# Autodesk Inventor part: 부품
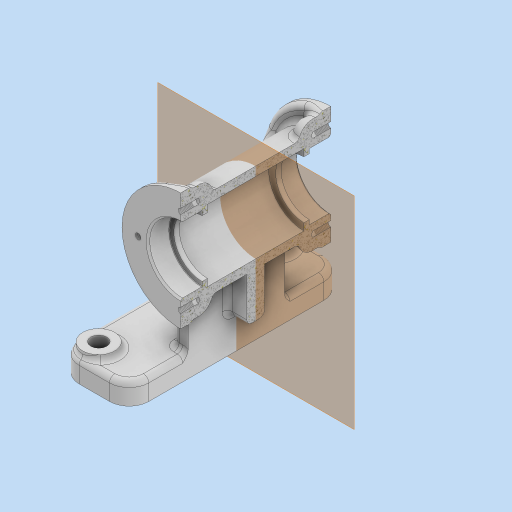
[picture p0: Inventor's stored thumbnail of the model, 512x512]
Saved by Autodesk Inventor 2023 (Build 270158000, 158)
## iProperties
Created: 2026-06
Part Number: 부품
Material: 일반
Document SubType Name: Modeling
Designer: home
Density: 1 g/cm^3
Appearance: 기본값
Author: home
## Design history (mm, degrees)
sketch "스케치1"
  geometry: L1 (50, 60)-(-50, 60); L2 (-50, 60)-(-50, -60); L3 (-50, -60)-(50, -60); L4 (50, -60)-(50, 60); L5 (50, 60)-(-50, -60); L6 (-50, 60)-(50, -60); 1 further point
  constraints: 12 end point, 2 midpoint, 2 parallel, 1 horizontal, 1 perpendicular
  dimensions: "d0" = 100 distance of L2.end L3.end; "d1" = 120 distance of L3.end L1.start
extrude "돌출1" new body sketch "스케치1" distance "d2" = 12; taper "d3" = 0 deg
sketch "스케치2"
  geometry: L1 (-11, 60)-(-11, -60); L2 (11, 60)-(11, -60); L3 (-50, 60)-(-50, -60) reference; L4 (50, -60)-(50, 60) reference; L5 (50, 60)-(-50, 60) reference; L6 (-11, 60)-(11, 60); L7 (-50, -60)-(50, -60) reference; L8 (-11, -60)-(11, -60); 1 further point
  constraints: 8 end point, 4 point on line, 2 vertical
  dimensions: "d4" = 39 distance between parallel lines of L1 L3; "d5" = 39 distance between parallel lines of L2 L4
extrude "돌출2" cut sketch "스케치2" extent not by distance; stored distance "d6" = 0; taper "d7" = 0 deg
node "작업 평면1"
node "작업 평면2"
sketch "스케치7"
  geometry: C1 r 33 at (0, 70); 1 further point
  constraints: 1 centre point, 1 vertical alignment
  dimensions: "d16" = 66 diameter of C1; "d17" = 70 distance of point (0, 0) C1.centre
extrude "돌출3" join sketch "스케치7" distance "d18" = 5; taper "d19" = 0 deg
sketch "스케치8"
  geometry: L1 (37, -37)-(103, -37) reference; L2 (37, 37)-(103, 37) reference; L3 (70, -37)-(70, 37); L4 (95, -37)-(95, 37); L5 (95, -37)-(70, -37); L6 (70, 37)-(70, -37); L7 (70, 37)-(95, 37); L8 (70, -37)-(70, 37); L9 (103, 42)-(37, 42) reference; 1 further point
  constraints: 12 end point, 3 collinear, 2 midpoint, 2 perpendicular, 2 point on line
  dimensions: "d20" = 50 diameter of L4 L3
revolve "회전2" sketch "스케치8" stored, may be unused: angle "d21" = 90 deg
sketch "스케치11"
  geometry: L1 (103, 42)-(37, 42) reference; L2 (88.5, 42)-(88.5, 30); L3 (88.5, 30)-(86, 30); L4 (86, 30)-(86, 27); L5 (86, 27)-(90, 27); L6 (90, 27)-(90, 0); L7 (95, -37)-(95, 37) reference; L8 (95, 0)-(37, 0); L9 (70, 42)-(70, -47.015); L10 (88.5, 42)-(70, 42); L11 (37, 37)-(103, 37) reference; L12 (70, 42)-(70, 0); L13 (70, 0)-(90, 0); 1 further point
  constraints: 20 end point, 5 perpendicular, 4 point on line, 2 midpoint, 1 collinear, 1 horizontal, 1 parallel, 1 vertical
  dimensions: "d22" = 32 diameter of L4 L9; "d23" = 37 diameter of L2 L9; "d24" = 12 distance of L2.start L2.end; "d25" = 27 distance of L5.end L6.end; "d26" = 40 diameter of L6 L9
revolve "회전3" sketch "스케치11" stored, may be unused: angle "d27" = 90 deg
fillet "모깎기1" dims "d28" = 11
sketch "스케치13"
  geometry: L1 (11, 27)-(19, 27); L2 (19, 27)-(19, -27); L3 (19, -27)-(11, -27); L4 (11, -27)-(11, 27); L5 (11, 49)-(11, -49) reference; 2 further points
  constraints: 8 end point, 2 midpoint, 2 parallel, 1 collinear, 1 horizontal, 1 perpendicular
  dimensions: "d32" = 54 distance of L3.end L1.start; "d41" = 8 distance between parallel lines of L2 L4
extrude "돌출4" join sketch "스케치13" stored distance "d34" = 5; taper "d35" = 0 deg
sketch "스케치14"
  geometry: L1 (24.587, 65.475)-(43, 12); L2 (19, 12)-(19, 53.752) reference; L3 (19, 12)-(19, 53.752); L4 (19, 12)-(43, 12); L5 (50, 12)-(50, 0) reference; A1 r 25 centre (0, 70) between (19, 53.752) and (19, 53.752) reference; A2 r 25 centre (0, 70) between (19, 53.752) and (24.587, 65.475); 2 further points
  constraints: 6 end point, 4 point on circle, 1 centre point, 1 coincident, 1 horizontal, 1 point on line
  dimensions: "d44" = 19 deg angle of L2 L1; "d45" = 7 distance from line of L1.end L5
extrude "돌출5" join sketch "스케치14" stored distance "d38" = 10; taper "d39" = 0 deg
fillet "모깎기3" dims "d40" = 3
sketch "스케치15"
  geometry: L1 (-39, -49)-(39, -49); L2 (39, -49)-(39, 49); L3 (39, 49)-(-39, 49); L4 (-39, 49)-(-39, -49); L5 (-39, -49)-(39, 49); L6 (39, -49)-(-39, 49); C1 r 9 at (-39, 49); C2 r 9 at (39, 49); C3 r 9 at (-39, -49); C4 r 9 at (39, -49); C5 r 4.5 at (-39, 49); C6 r 4.5 at (39, 49); C7 r 4.5 at (39, -49); C8 r 4.5 at (-39, -49); 1 further point
  constraints: 12 end point, 8 centre point, 8 coincident, 2 midpoint, 2 parallel, 1 horizontal, 1 perpendicular
  dimensions: "d46" = 78 distance of L2.end L3.end; "d47" = 98 distance of L3.end L1.start; "d48" = 18 diameter of C1; "d49" = 18 diameter of C2; "d50" = 18 diameter of C3; "d51" = 18 diameter of C4; "d54" = 9 diameter of C5; "d55" = 9 diameter of C6; "d56" = 9 diameter of C7; "d57" = 9 diameter of C8
extrude "돌출6" join sketch "스케치15" distance "d52" = 3; taper "d53" = 0 deg
feature "면 삭제1"
extrude "돌출7" cut sketch "스케치15" extent not by distance; stored distance "d58" = 0; taper "d59" = 0 deg
fillet "모깎기4" dims "d60" = 3
sketch "스케치16"
  geometry: C1 r 33 at (0, 0) reference; A1 r 24 centre (0, 0) between (-24, 0) and (0, -24); 3 further points
  constraints: 4 point on circle, 2 horizontal alignment, 2 vertical alignment, 1 centre point, 1 coincident
  dimensions: "d68" = 48 diameter of A1
sketch "스케치17"
  geometry: L1 (92.379, 42)-(95.621, 42) reference; L2 (94, 42)-(94, 29); L3 (94, 37)-(94, 19.967); C1 r 8 at (94, 32); 4 further points
  constraints: 4 end point, 2 point on line, 2 vertical, 1 centre point, 1 midpoint
  dimensions: "d75" = 16 diameter of C1; "d76" = 10 distance from line of C1.centre L1
revolve "회전4" sketch "스케치17" stored, may be unused: angle "d77" = 90 deg
fillet "모깎기5" dims "d83" = 3
sketch "스케치18"
  geometry: C1 r 18.5 at (0, 0) reference; C2 r 18.5 at (0, 0); 1 further point
  constraints: 1 centre point, 1 coincident, 1 concentric
extrude "돌출8" cut sketch "스케치18" stored distance "d78" = 10; taper "d79" = 0 deg
sketch "스케치22"
  geometry: C1 r 16 at (0, -24) reference; C2 r 20 at (0, -24); 1 further point
  constraints: 1 centre point, 1 coincident
  dimensions: "d85" = 40 diameter of C2
extrude "돌출9" cut sketch "스케치22" stored distance "d86" = 10; taper "d87" = 0 deg
sketch "스케치23"
  geometry: L1 (0, -49)-(0, 49) reference; 3 further points
  constraints: 1 horizontal alignment, 1 midpoint, 1 other
  dimensions: "d88" = 70 distance from line of point (70, 0) L1
feature "엠보싱1" sketch "스케치23" dims "d89" = 0.5, "d90" = 0
chamfer "모따기1" distance "d91" = 1; stored, may be unused: second distance "d92" = 2, angle "d93" = 45 deg
fillet "모깎기6" dims "d94" = 0.3
sketch "스케치24"
  geometry: L1 (-9, 20)-(8, 20); L2 (22, 52.679)-(22, 15) reference; L3 (-11, 14.196)-(-11, 47.55) reference; L4 (11, 14.196)-(11, 47.55) reference; L5 (-11, 48.629)-(11, 48.629); L6 (-11, 48.629)-(-11, 18); L7 (11, 48.629)-(11, 17); A1 r 25 centre (0, 70) between (9.508, 46.879) and (23.121, 60.492) reference; A2 r 25 centre (0, 70) between (-23.121, 60.492) and (-9.508, 46.879) reference; A3 r 2 centre (-9, 18) between (-9, 20) and (-11, 18); A4 r 3 centre (8, 17) between (11, 17) and (8, 20); 9 further points
  constraints: 8 end point, 4 point on circle, 3 point on line, 2 centre point, 2 tangent, 2 vertical, 1 horizontal, 1 horizontal alignment
  dimensions: "d95" = 20 distance from line of point (0, 0) L1; "d98" = 2 radius of A3 (derived); "d99" = 3 radius of A4 (derived)
extrude "돌출10" join sketch "스케치24" stored distance "d96" = 10; taper "d97" = 0 deg
fillet "모깎기7" dims "d100" = 3
hole "구멍2" sketch "스케치16" diameter "d101" = 3.242; stored, may be unused: countersink angle "d105" = 90 deg, drill point angle "d107" = 118 deg; dims "d102" = 8, "d103" = 4, "d104" = 2, "d106" = 10
node "솔리드1"
mirror "미러1"
mirror "미러2"
mirror "미러3"
mirror "미러4"
pattern_circular "원형 패턴1" dims angle "d81" = 360 deg
mirror "미러6"
mirror "미러7"
mirror "미러8"
feature "A9D066F2-1C7D-4E18-AEED-F7BC21143FA4" dims "d101" = 3.242, "d102" = 8, "d103" = 4, "d104" = 2, "d105" = 90 deg, "d106" = 10, "d107" = 118 deg
other parameters: "d15" = 42
